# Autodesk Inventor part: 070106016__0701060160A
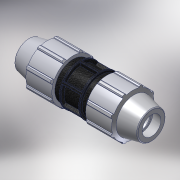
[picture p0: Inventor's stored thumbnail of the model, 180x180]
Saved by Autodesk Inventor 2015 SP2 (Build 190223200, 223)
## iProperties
Created: 2017-02
Part Number: 070106016__0701060160A
Material: PVC-Piping
Description: PLASSON COUPLER 16-16
Document SubType Name: Modeling
Designer: KIM
Mass: 92.6774 g
Surface Area: 199.44 cm^2
Volume: 66.1981 cm^3
Density: 1.4 g/cm^3
Appearance: PTFE
Author: KIM
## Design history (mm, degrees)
derived "07010.ipt"
feature "Solid1::07010.ipt"
tag "TaggingFeature1"
body "Solid1"
other parameters: "d1" = 105, "d2" = 16, "d4" = 8.75, "d5" = 15, "d7" = 39, "d8" = 29.25, "d9" = 15, "d11" = 1.5, "d12" = 31.2, "d13" = 120 deg, "d14" = 24, "d15" = 12 deg, "d16" = 35.1, "d18" = 0.8, "d19" = 35 deg, "d20" = 17.5 deg, "d21" = 36.27, "d23" = 0, "d25" = 360 deg, "d27" = 0.78, "d33" = 0.32, "d34" = 1.95, "d36" = 0, "d37" = 0.32, "d38" = 0.32, "d40" = 360 deg, "d42" = 23.1, "d43" = 1.17, "d46" = 0.48, "d50" = 12.8, "d_" = 16, "E_" = 39, "H_" = 105
